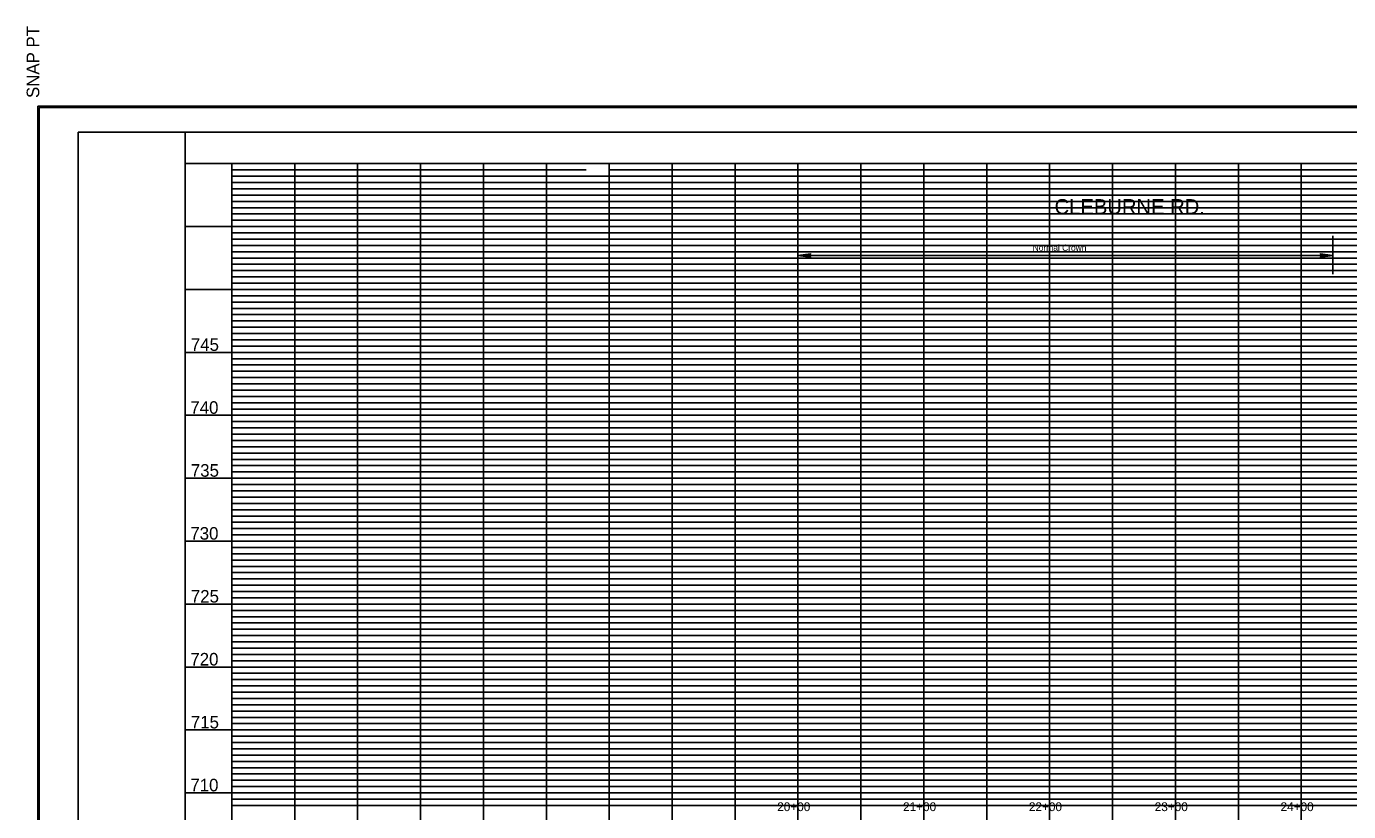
# Model space of a CAD drawing. Extents: x -200 to 1681865, y -325 to 520634.
# Drawn here: x 1680154 to 1681205, y 520010 to 520634 of the extents above; entities that cross this region are included whole.
import ezdxf

# ---------------------------------------------------------------- set-up
doc = ezdxf.new("R2010")
doc.units = 0
for name, color, linetype in [('DESIGN - PROFILE - Proposed Text', 7, 'Continuous'), ('DESIGN - SHEET - Corner Text', 7, 'Continuous'), ('DESIGN - SHEET - Light Grid', 7, 'Continuous'), ('DESIGN - SHEET - Linework', 7, 'Continuous'), ('DESIGN - SHEET - Plot Shape', 7, 'Continuous')]:
    doc.layers.add(name, color=color, linetype=linetype)

msp = doc.modelspace()

# ---------------------------------------------------------------- linework, layer by layer
at = {"layer": 'DESIGN - PROFILE - Proposed Text'}
for p, q in [((1681192.1, 520436.9), (1681192.1, 520467.4)), ((1680767.1, 520451.9), (1681192.1, 520451.9))]:
    msp.add_line(p, q, dxfattribs=at)
for points in [[(1680767.1, 520451.9), (1680777.2, 520453.2), (1680775.9, 520451.9), (1680777.2, 520450.6)], [(1681192.1, 520451.9), (1681182.1, 520453.2), (1681183.4, 520451.9), (1681182.1, 520450.6)]]:
    msp.add_lwpolyline(points, close=True, dxfattribs=at)
for points in [[(1680767.1, 520451.9), (1680777.2, 520453.2), (1680775.9, 520451.9), (1680777.2, 520450.6), (1680767.1, 520451.9)], [(1681192.1, 520451.9), (1681182.1, 520453.2), (1681183.4, 520451.9), (1681182.1, 520450.6), (1681192.1, 520451.9)]]:
    msp.add_lwpolyline(points, dxfattribs=at)
at = {"layer": 'DESIGN - SHEET - Light Grid'}
for p, q in [((1680317.1, 520519.8), (1680598.7, 520519.8)), ((1680617.1, 520519.8), (1680967.1, 520519.8)), ((1680967.1, 520519.8), (1681317.1, 520519.8)), ((1680317.1, 520514.8), (1680617.1, 520514.8)), ((1680317.1, 520509.8), (1680617.1, 520509.8)), ((1680617.1, 520514.8), (1680967.1, 520514.8)), ((1680617.1, 520509.8), (1680967.1, 520509.8)), ((1680967.1, 520514.8), (1681317.1, 520514.8)), ((1680967.1, 520509.8), (1681317.1, 520509.8)), ((1680317.1, 520504.8), (1680617.1, 520504.8)), ((1680317.1, 520499.8), (1680617.1, 520499.8)), ((1680617.1, 520504.8), (1680967.1, 520504.8)), ((1680617.1, 520499.8), (1680967.1, 520499.8)), ((1680967.1, 520504.8), (1681317.1, 520504.8)), ((1680967.1, 520499.8), (1681317.1, 520499.8)), ((1680317.1, 520494.8), (1680617.1, 520494.8)), ((1680317.1, 520489.8), (1680617.1, 520489.8)), ((1680317.1, 520484.8), (1680617.1, 520484.8)), ((1680617.1, 520494.8), (1680967.1, 520494.8)), ((1680617.1, 520489.8), (1680967.1, 520489.8)), ((1680617.1, 520484.8), (1680967.1, 520484.8)), ((1680967.1, 520494.8), (1681317.1, 520494.8)), ((1680967.1, 520489.8), (1681317.1, 520489.8)), ((1680967.1, 520484.8), (1681317.1, 520484.8)), ((1680317.1, 520479.8), (1680617.1, 520479.8)), ((1680617.1, 520479.8), (1680967.1, 520479.8)), ((1680967.1, 520479.8), (1681317.1, 520479.8)), ((1680317.1, 520469.8), (1680617.1, 520469.8)), ((1680317.1, 520464.8), (1680617.1, 520464.8)), ((1680617.1, 520469.8), (1680967.1, 520469.8)), ((1680617.1, 520464.8), (1680967.1, 520464.8)), ((1680967.1, 520469.8), (1681317.1, 520469.8)), ((1680967.1, 520464.8), (1681317.1, 520464.8)), ((1680317.1, 520459.8), (1680617.1, 520459.8)), ((1680317.1, 520454.8), (1680617.1, 520454.8)), ((1680617.1, 520459.8), (1680967.1, 520459.8)), ((1680617.1, 520454.8), (1680967.1, 520454.8)), ((1680967.1, 520459.8), (1681317.1, 520459.8)), ((1680967.1, 520454.8), (1681317.1, 520454.8)), ((1680317.1, 520449.8), (1680617.1, 520449.8)), ((1680317.1, 520444.8), (1680617.1, 520444.8)), ((1680617.1, 520449.8), (1680967.1, 520449.8)), ((1680617.1, 520444.8), (1680967.1, 520444.8)), ((1680967.1, 520449.8), (1681317.1, 520449.8)), ((1680967.1, 520444.8), (1681317.1, 520444.8)), ((1680317.1, 520439.8), (1680617.1, 520439.8)), ((1680317.1, 520434.8), (1680617.1, 520434.8)), ((1680617.1, 520439.8), (1680967.1, 520439.8)), ((1680617.1, 520434.8), (1680967.1, 520434.8)), ((1680967.1, 520439.8), (1681317.1, 520439.8)), ((1680967.1, 520434.8), (1681317.1, 520434.8)), ((1680317.1, 520429.8), (1680617.1, 520429.8)), ((1680617.1, 520429.8), (1680967.1, 520429.8)), ((1680967.1, 520429.8), (1681317.1, 520429.8)), ((1680317.1, 520419.8), (1680617.1, 520419.8)), ((1680317.1, 520414.8), (1680617.1, 520414.8)), ((1680617.1, 520419.8), (1680967.1, 520419.8)), ((1680617.1, 520414.8), (1680967.1, 520414.8)), ((1680967.1, 520419.8), (1681317.1, 520419.8)), ((1680967.1, 520414.8), (1681317.1, 520414.8)), ((1680317.1, 520409.8), (1680617.1, 520409.8)), ((1680317.1, 520404.8), (1680617.1, 520404.8)), ((1680617.1, 520409.8), (1680967.1, 520409.8)), ((1680617.1, 520404.8), (1680967.1, 520404.8)), ((1680967.1, 520409.8), (1681317.1, 520409.8)), ((1680967.1, 520404.8), (1681317.1, 520404.8)), ((1680317.1, 520399.8), (1680617.1, 520399.8)), ((1680317.1, 520394.8), (1680617.1, 520394.8)), ((1680617.1, 520399.8), (1680967.1, 520399.8)), ((1680617.1, 520394.8), (1680967.1, 520394.8)), ((1680967.1, 520399.8), (1681317.1, 520399.8)), ((1680967.1, 520394.8), (1681317.1, 520394.8)), ((1680317.1, 520389.8), (1680617.1, 520389.8)), ((1680317.1, 520384.8), (1680617.1, 520384.8)), ((1680317.1, 520379.8), (1680617.1, 520379.8)), ((1680617.1, 520389.8), (1680967.1, 520389.8)), ((1680617.1, 520384.8), (1680967.1, 520384.8)), ((1680617.1, 520379.8), (1680967.1, 520379.8)), ((1680967.1, 520389.8), (1681317.1, 520389.8)), ((1680967.1, 520384.8), (1681317.1, 520384.8)), ((1680967.1, 520379.8), (1681317.1, 520379.8)), ((1680317.1, 520369.8), (1680617.1, 520369.8)), ((1680617.1, 520369.8), (1680967.1, 520369.8)), ((1680967.1, 520369.8), (1681317.1, 520369.8)), ((1680317.1, 520364.8), (1680617.1, 520364.8)), ((1680317.1, 520359.8), (1680617.1, 520359.8)), ((1680617.1, 520364.8), (1680967.1, 520364.8)), ((1680617.1, 520359.8), (1680967.1, 520359.8)), ((1680967.1, 520364.8), (1681317.1, 520364.8)), ((1680967.1, 520359.8), (1681317.1, 520359.8)), ((1680317.1, 520354.8), (1680617.1, 520354.8)), ((1680317.1, 520349.8), (1680617.1, 520349.8)), ((1680617.1, 520354.8), (1680967.1, 520354.8)), ((1680617.1, 520349.8), (1680967.1, 520349.8)), ((1680967.1, 520354.8), (1681317.1, 520354.8)), ((1680967.1, 520349.8), (1681317.1, 520349.8)), ((1680317.1, 520344.8), (1680617.1, 520344.8)), ((1680317.1, 520339.8), (1680617.1, 520339.8)), ((1680617.1, 520344.8), (1680967.1, 520344.8)), ((1680617.1, 520339.8), (1680967.1, 520339.8)), ((1680967.1, 520344.8), (1681317.1, 520344.8)), ((1680967.1, 520339.8), (1681317.1, 520339.8)), ((1680317.1, 520334.8), (1680617.1, 520334.8)), ((1680317.1, 520329.8), (1680617.1, 520329.8)), ((1680617.1, 520334.8), (1680967.1, 520334.8)), ((1680617.1, 520329.8), (1680967.1, 520329.8)), ((1680967.1, 520334.8), (1681317.1, 520334.8)), ((1680967.1, 520329.8), (1681317.1, 520329.8)), ((1680317.1, 520319.8), (1680617.1, 520319.8)), ((1680617.1, 520319.8), (1680967.1, 520319.8)), ((1680967.1, 520319.8), (1681317.1, 520319.8)), ((1680317.1, 520314.8), (1680617.1, 520314.8)), ((1680317.1, 520309.8), (1680617.1, 520309.8)), ((1680617.1, 520314.8), (1680967.1, 520314.8)), ((1680617.1, 520309.8), (1680967.1, 520309.8)), ((1680967.1, 520314.8), (1681317.1, 520314.8)), ((1680967.1, 520309.8), (1681317.1, 520309.8)), ((1680317.1, 520304.8), (1680617.1, 520304.8)), ((1680317.1, 520299.8), (1680617.1, 520299.8)), ((1680617.1, 520304.8), (1680967.1, 520304.8)), ((1680617.1, 520299.8), (1680967.1, 520299.8)), ((1680967.1, 520304.8), (1681317.1, 520304.8)), ((1680967.1, 520299.8), (1681317.1, 520299.8)), ((1680317.1, 520294.8), (1680617.1, 520294.8)), ((1680317.1, 520289.8), (1680617.1, 520289.8)), ((1680617.1, 520294.8), (1680967.1, 520294.8)), ((1680617.1, 520289.8), (1680967.1, 520289.8)), ((1680967.1, 520294.8), (1681317.1, 520294.8)), ((1680967.1, 520289.8), (1681317.1, 520289.8)), ((1680317.1, 520284.8), (1680617.1, 520284.8)), ((1680317.1, 520279.8), (1680617.1, 520279.8)), ((1680617.1, 520284.8), (1680967.1, 520284.8)), ((1680617.1, 520279.8), (1680967.1, 520279.8)), ((1680967.1, 520284.8), (1681317.1, 520284.8)), ((1680967.1, 520279.8), (1681317.1, 520279.8)), ((1680317.1, 520269.8), (1680617.1, 520269.8)), ((1680317.1, 520264.8), (1680617.1, 520264.8)), ((1680617.1, 520269.8), (1680967.1, 520269.8)), ((1680617.1, 520264.8), (1680967.1, 520264.8)), ((1680967.1, 520269.8), (1681317.1, 520269.8)), ((1680967.1, 520264.8), (1681317.1, 520264.8)), ((1680317.1, 520259.8), (1680617.1, 520259.8)), ((1680317.1, 520254.8), (1680617.1, 520254.8)), ((1680617.1, 520259.8), (1680967.1, 520259.8)), ((1680617.1, 520254.8), (1680967.1, 520254.8)), ((1680967.1, 520259.8), (1681317.1, 520259.8)), ((1680967.1, 520254.8), (1681317.1, 520254.8)), ((1680317.1, 520249.8), (1680617.1, 520249.8)), ((1680317.1, 520244.8), (1680617.1, 520244.8)), ((1680617.1, 520249.8), (1680967.1, 520249.8)), ((1680617.1, 520244.8), (1680967.1, 520244.8)), ((1680967.1, 520249.8), (1681317.1, 520249.8)), ((1680967.1, 520244.8), (1681317.1, 520244.8)), ((1680317.1, 520239.8), (1680617.1, 520239.8)), ((1680317.1, 520234.8), (1680617.1, 520234.8)), ((1680617.1, 520239.8), (1680967.1, 520239.8)), ((1680617.1, 520234.8), (1680967.1, 520234.8)), ((1680967.1, 520239.8), (1681317.1, 520239.8)), ((1680967.1, 520234.8), (1681317.1, 520234.8)), ((1680317.1, 520229.8), (1680617.1, 520229.8)), ((1680617.1, 520229.8), (1680967.1, 520229.8)), ((1680967.1, 520229.8), (1681317.1, 520229.8)), ((1680317.1, 520219.8), (1680617.1, 520219.8)), ((1680317.1, 520214.8), (1680617.1, 520214.8)), ((1680617.1, 520219.8), (1680967.1, 520219.8)), ((1680617.1, 520214.8), (1680967.1, 520214.8)), ((1680967.1, 520219.8), (1681317.1, 520219.8)), ((1680967.1, 520214.8), (1681317.1, 520214.8)), ((1680317.1, 520209.8), (1680617.1, 520209.8)), ((1680317.1, 520204.8), (1680617.1, 520204.8)), ((1680617.1, 520209.8), (1680967.1, 520209.8)), ((1680617.1, 520204.8), (1680967.1, 520204.8)), ((1680967.1, 520209.8), (1681317.1, 520209.8)), ((1680967.1, 520204.8), (1681317.1, 520204.8)), ((1680317.1, 520199.8), (1680617.1, 520199.8)), ((1680317.1, 520194.8), (1680617.1, 520194.8)), ((1680617.1, 520199.8), (1680967.1, 520199.8)), ((1680617.1, 520194.8), (1680967.1, 520194.8)), ((1680967.1, 520199.8), (1681317.1, 520199.8)), ((1680967.1, 520194.8), (1681317.1, 520194.8)), ((1680317.1, 520189.8), (1680617.1, 520189.8)), ((1680317.1, 520184.8), (1680617.1, 520184.8)), ((1680617.1, 520189.8), (1680967.1, 520189.8)), ((1680617.1, 520184.8), (1680967.1, 520184.8)), ((1680967.1, 520189.8), (1681317.1, 520189.8)), ((1680967.1, 520184.8), (1681317.1, 520184.8)), ((1680317.1, 520179.8), (1680617.1, 520179.8)), ((1680317.1, 520169.8), (1680617.1, 520169.8)), ((1680617.1, 520179.8), (1680967.1, 520179.8)), ((1680617.1, 520169.8), (1680967.1, 520169.8)), ((1680967.1, 520179.8), (1681317.1, 520179.8)), ((1680967.1, 520169.8), (1681317.1, 520169.8)), ((1680317.1, 520164.8), (1680617.1, 520164.8)), ((1680317.1, 520159.8), (1680617.1, 520159.8)), ((1680617.1, 520164.8), (1680967.1, 520164.8)), ((1680617.1, 520159.8), (1680967.1, 520159.8)), ((1680967.1, 520164.8), (1681317.1, 520164.8)), ((1680967.1, 520159.8), (1681317.1, 520159.8)), ((1680317.1, 520154.8), (1680617.1, 520154.8)), ((1680317.1, 520149.8), (1680617.1, 520149.8)), ((1680617.1, 520154.8), (1680967.1, 520154.8)), ((1680617.1, 520149.8), (1680967.1, 520149.8)), ((1680967.1, 520154.8), (1681317.1, 520154.8)), ((1680967.1, 520149.8), (1681317.1, 520149.8)), ((1680317.1, 520144.8), (1680617.1, 520144.8)), ((1680317.1, 520139.8), (1680617.1, 520139.8)), ((1680617.1, 520144.8), (1680967.1, 520144.8)), ((1680617.1, 520139.8), (1680967.1, 520139.8)), ((1680967.1, 520144.8), (1681317.1, 520144.8)), ((1680967.1, 520139.8), (1681317.1, 520139.8)), ((1680317.1, 520134.8), (1680617.1, 520134.8)), ((1680317.1, 520129.8), (1680617.1, 520129.8)), ((1680617.1, 520134.8), (1680967.1, 520134.8)), ((1680617.1, 520129.8), (1680967.1, 520129.8)), ((1680967.1, 520134.8), (1681317.1, 520134.8)), ((1680967.1, 520129.8), (1681317.1, 520129.8)), ((1680317.1, 520119.8), (1680617.1, 520119.8)), ((1680617.1, 520119.8), (1680967.1, 520119.8)), ((1680967.1, 520119.8), (1681317.1, 520119.8)), ((1680317.1, 520114.8), (1680617.1, 520114.8)), ((1680317.1, 520109.8), (1680617.1, 520109.8)), ((1680617.1, 520114.8), (1680967.1, 520114.8)), ((1680617.1, 520109.8), (1680967.1, 520109.8)), ((1680967.1, 520114.8), (1681317.1, 520114.8)), ((1680967.1, 520109.8), (1681317.1, 520109.8)), ((1680317.1, 520104.8), (1680617.1, 520104.8)), ((1680317.1, 520099.8), (1680617.1, 520099.8)), ((1680617.1, 520104.8), (1680967.1, 520104.8)), ((1680617.1, 520099.8), (1680967.1, 520099.8)), ((1680967.1, 520104.8), (1681317.1, 520104.8)), ((1680967.1, 520099.8), (1681317.1, 520099.8)), ((1680317.1, 520094.8), (1680617.1, 520094.8)), ((1680317.1, 520089.8), (1680617.1, 520089.8)), ((1680617.1, 520094.8), (1680967.1, 520094.8)), ((1680617.1, 520089.8), (1680967.1, 520089.8)), ((1680967.1, 520094.8), (1681317.1, 520094.8)), ((1680967.1, 520089.8), (1681317.1, 520089.8)), ((1680317.1, 520084.8), (1680617.1, 520084.8)), ((1680317.1, 520079.8), (1680617.1, 520079.8)), ((1680617.1, 520084.8), (1680967.1, 520084.8)), ((1680617.1, 520079.8), (1680967.1, 520079.8)), ((1680967.1, 520084.8), (1681317.1, 520084.8)), ((1680967.1, 520079.8), (1681317.1, 520079.8)), ((1680317.1, 520069.8), (1680617.1, 520069.8)), ((1680317.1, 520064.8), (1680617.1, 520064.8)), ((1680617.1, 520069.8), (1680967.1, 520069.8)), ((1680617.1, 520064.8), (1680967.1, 520064.8)), ((1680967.1, 520069.8), (1681317.1, 520069.8)), ((1680967.1, 520064.8), (1681317.1, 520064.8)), ((1680317.1, 520059.8), (1680617.1, 520059.8)), ((1680317.1, 520054.8), (1680617.1, 520054.8)), ((1680617.1, 520059.8), (1680967.1, 520059.8)), ((1680617.1, 520054.8), (1680967.1, 520054.8)), ((1680967.1, 520059.8), (1681317.1, 520059.8)), ((1680967.1, 520054.8), (1681317.1, 520054.8)), ((1680317.1, 520049.8), (1680617.1, 520049.8)), ((1680317.1, 520044.8), (1680617.1, 520044.8)), ((1680617.1, 520049.8), (1680967.1, 520049.8)), ((1680617.1, 520044.8), (1680967.1, 520044.8)), ((1680967.1, 520049.8), (1681317.1, 520049.8)), ((1680967.1, 520044.8), (1681317.1, 520044.8)), ((1680317.1, 520039.8), (1680617.1, 520039.8)), ((1680317.1, 520034.8), (1680617.1, 520034.8)), ((1680617.1, 520039.8), (1680967.1, 520039.8)), ((1680617.1, 520034.8), (1680967.1, 520034.8)), ((1680967.1, 520039.8), (1681317.1, 520039.8)), ((1680967.1, 520034.8), (1681317.1, 520034.8)), ((1680317.1, 520029.8), (1680617.1, 520029.8)), ((1680617.1, 520029.8), (1680967.1, 520029.8)), ((1680967.1, 520029.8), (1681317.1, 520029.8)), ((1680317.1, 520019.8), (1680617.1, 520019.8)), ((1680317.1, 520014.8), (1680617.1, 520014.8)), ((1680617.1, 520019.8), (1680967.1, 520019.8)), ((1680617.1, 520014.8), (1680967.1, 520014.8)), ((1680967.1, 520019.8), (1681317.1, 520019.8)), ((1680967.1, 520014.8), (1681317.1, 520014.8))]:
    msp.add_line(p, q, dxfattribs=at)
at = {"layer": 'DESIGN - SHEET - Linework'}
for p, q in [((1680163.1, 519479.1), (1680163.1, 520570.5)), ((1680163.1, 520570.5), (1681865.1, 520570.5)), ((1680282.1, 520524.8), (1681654.2, 520524.8)), ((1680317.1, 519524.8), (1680317.1, 520524.8)), ((1680367.1, 519524.8), (1680367.1, 520524.8)), ((1680417.1, 519524.8), (1680417.1, 520524.8)), ((1680467.1, 519524.8), (1680467.1, 520524.8)), ((1680517.1, 519524.8), (1680517.1, 520524.8)), ((1680567.1, 519524.8), (1680567.1, 520524.8)), ((1680617.1, 519524.8), (1680617.1, 520524.8)), ((1680667.1, 519524.8), (1680667.1, 520524.8)), ((1680717.1, 519524.8), (1680717.1, 520524.8)), ((1680767.1, 519524.8), (1680767.1, 520524.8)), ((1680817.1, 519524.8), (1680817.1, 520524.8)), ((1680867.1, 519524.8), (1680867.1, 520524.8)), ((1680917.1, 519524.8), (1680917.1, 520524.8)), ((1680967.1, 519524.8), (1680967.1, 520524.8)), ((1681017.1, 519524.8), (1681017.1, 520524.8)), ((1681067.1, 519524.8), (1681067.1, 520524.8)), ((1681117.1, 519524.8), (1681117.1, 520524.8)), ((1681167.1, 519524.8), (1681167.1, 520524.8)), ((1680280, 520474.8), (1681654.2, 520474.8)), ((1680280, 520424.8), (1681654.2, 520424.8)), ((1680280, 520374.8), (1681654.2, 520374.8)), ((1680280, 520324.8), (1681654.2, 520324.8)), ((1680280, 520274.8), (1681654.2, 520274.8)), ((1680280, 520224.8), (1681654.2, 520224.8)), ((1680280, 520174.8), (1681654.2, 520174.8)), ((1680280, 520124.8), (1681654.2, 520124.8)), ((1680280, 520074.8), (1681654.2, 520074.8)), ((1680280, 520024.8), (1681654.2, 520024.8))]:
    msp.add_line(p, q, dxfattribs=at)
for points in [[(1680280, 520549.8), (1680280, 519499.8), (1681854.2, 519499.8), (1681854.2, 520549.8), (1680280, 520549.8)], [(1680280, 519524.8), (1680280, 520524.8), (1681654.2, 520524.8), (1681654.2, 519524.8), (1680282.1, 519524.8)]]:
    msp.add_lwpolyline(points, dxfattribs=at)
at = {"layer": 'DESIGN - SHEET - Plot Shape'}
for points in [[(1680164.1, 520569.5), (1681864.1, 520569.5), (1681864.1, 519480.1), (1680164.1, 519480.1)], [(1680195, 520549.8), (1681854.2, 520549.8), (1681854.2, 519499.8), (1680195, 519499.8)]]:
    msp.add_lwpolyline(points, close=True, dxfattribs=at)

# ---------------------------------------------------------------- texts
at = {"layer": 'DESIGN - PROFILE - Proposed Text'}
for s, height, p in [('CLEBURNE RD.', 12, (1680971, 520484.6)), ('Normal Crown', 5, (1680953.6, 520455.5))]:
    msp.add_text(s, height=height, dxfattribs=at).set_placement(p)
at = {"layer": 'DESIGN - SHEET - Corner Text'}
msp.add_text('  SNAP PT', height=10, rotation=90, dxfattribs=at).set_placement((1680164.1, 520569.5))
for s, height, p in [('745', 10, (1680284.6, 520376)), ('740', 10, (1680284.2, 520326)), ('735', 10, (1680284.6, 520276)), ('730', 10, (1680284.2, 520226)), ('725', 10, (1680284.6, 520176)), ('720', 10, (1680284.2, 520126)), ('715', 10, (1680284.6, 520076)), ('710', 10, (1680284.2, 520026)), ('20+00', 7, (1680750.6, 520010.3)), ('21+00', 7, (1680850.6, 520010.3)), ('22+00', 7, (1680950.6, 520010.3)), ('23+00', 7, (1681050.6, 520010.3)), ('24+00', 7, (1681150.6, 520010.3))]:
    msp.add_text(s, height=height, dxfattribs=at).set_placement(p)

doc.saveas('drawing.dxf')
